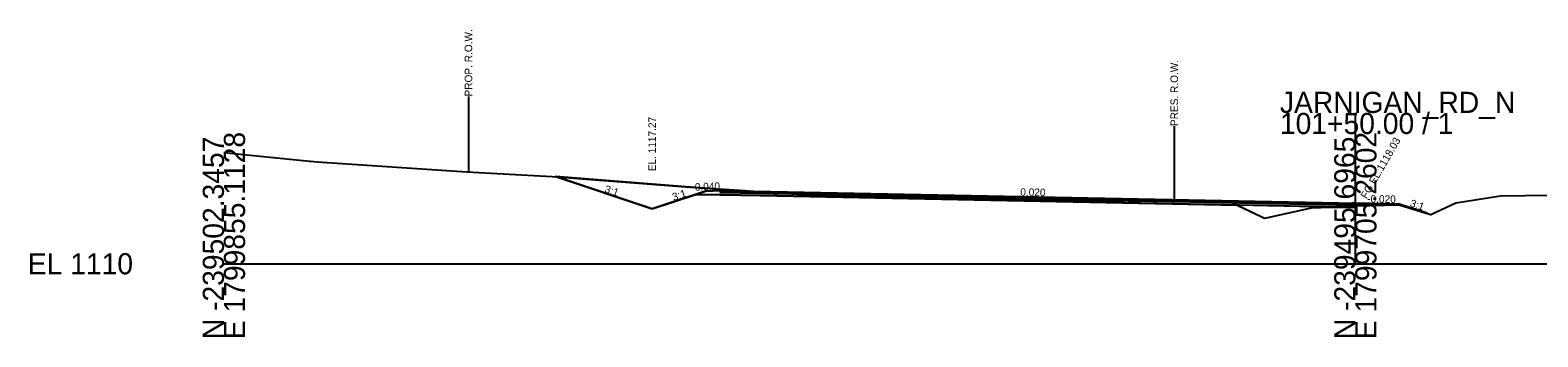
# Model space of a CAD drawing. Extents: x 214513 to 217151, y 214739 to 216780.
# Drawn here: x 216122.7 to 216322.6, y 214738.7 to 214779.3 of the extents above; entities that cross this region are included whole.
import ezdxf

# ---------------------------------------------------------------- set-up
doc = ezdxf.new("R2010")
doc.units = 0
for name, color, linetype in [('CONCEPT - TRANSPORTATION - Roads Text', 7, 'Continuous'), ('DESIGN - CENTERLINE - Proposed', 7, 'Continuous'), ('DESIGN - CENTERLINE - Proposed Text', 7, 'Continuous'), ('DESIGN - DRAINAGE - Special Ditches', 7, 'Continuous'), ('DESIGN - EARTHWORK - Shapes', 7, 'Continuous'), ('DESIGN - ROW - Right-of-Way Linework', 7, 'Continuous'), ('DESIGN - TRANSPORTATION - Text', 7, 'Continuous'), ('DESIGN - TYPICAL - Slope Tie Text', 7, 'Continuous'), ('Section', 7, 'Continuous'), ('SURVEY - DTM GRAPHICS - Triangles', 7, 'Continuous'), ('SURVEY - PROPERTY - ROW Lines', 7, 'Continuous'), ('XSCell', 7, 'Continuous')]:
    doc.layers.add(name, color=color, linetype=linetype)

msp = doc.modelspace()

# ---------------------------------------------------------------- linework, layer by layer
at = {"layer": 'DESIGN - DRAINAGE - Special Ditches'}
for points in [[(216205.13, 214755.64), (216192.3, 214759.92)], [(216212.21, 214758), (216205.13, 214755.64)], [(216214.21, 214758.08), (216214.21, 214757.83), (216219.5, 214757.72), (216298.36, 214756.14), (216298.36, 214755.81), (216219.5, 214757.39), (216214.21, 214757.5), (216210.91, 214757.56), (216212.21, 214758), (216214.21, 214758.08)], [(216214.21, 214758.08), (216298.36, 214756.39), (216298.36, 214756.29), (216298.36, 214756.29), (216214.21, 214757.98), (216214.21, 214757.98), (216214.21, 214757.98), (216214.21, 214758.08), (216214.21, 214758.08)], [(216214.21, 214757.98), (216298.36, 214756.29), (216298.36, 214756.14), (216298.36, 214756.14), (216214.21, 214757.83), (216214.21, 214757.83), (216214.21, 214757.83), (216214.21, 214757.98), (216214.21, 214757.98)], [(216304.16, 214756.28), (216298.36, 214756.39), (216298.36, 214756.29), (216298.36, 214756.29), (216304.16, 214756.18), (216304.16, 214756.18), (216304.16, 214756.18), (216304.16, 214756.28), (216304.16, 214756.28)], [(216304.16, 214756.28), (216307.86, 214755.05)]]:
    msp.add_lwpolyline(points, dxfattribs=at)
at = {"layer": 'DESIGN - EARTHWORK - Shapes'}
for p, q in [((216192.3, 214759.92), (216205.13, 214755.64)), ((216212.21, 214758), (216210.91, 214757.56)), ((216212.21, 214758), (216214.21, 214758.08)), ((216214.21, 214758.08), (216212.21, 214758)), ((216214.21, 214758.08), (216217.4, 214758.01)), ((216214.21, 214757.98), (216214.21, 214758.08)), ((216214.21, 214758.08), (216214.21, 214757.98)), ((216217.4, 214758.01), (216214.21, 214758.08)), ((216219.71, 214757.87), (216214.21, 214757.98)), ((216214.21, 214757.98), (216214.21, 214757.83)), ((216214.21, 214757.98), (216219.71, 214757.87)), ((216214.21, 214757.83), (216219.5, 214757.72)), ((216219.71, 214757.87), (216217.4, 214758.01)), ((216219.5, 214757.72), (216223.18, 214757.65)), ((216223.18, 214757.65), (216219.71, 214757.87)), ((216282, 214756.47), (216276.27, 214756.59)), ((216282.72, 214756.13), (216282, 214756.47)), ((216298.36, 214756.29), (216298.36, 214756.14)), ((216307.86, 214755.05), (216304.16, 214756.28)), ((216295.06, 214755.88), (216282.72, 214756.13)), ((216295.06, 214755.88), (216298.36, 214755.81)), ((216298.36, 214756.14), (216298.36, 214756.05)), ((216298.36, 214755.81), (216298.36, 214756.05))]:
    msp.add_line(p, q, dxfattribs=at)
for points in [[(216217.4, 214758.01), (216215.28, 214758.15), (216209.6, 214758.56), (216192.3, 214759.92)], [(216205.13, 214755.64), (216210.91, 214757.56), (216212.21, 214758)], [(216210.91, 214757.56), (216214.21, 214757.5), (216219.5, 214757.39), (216282.72, 214756.13)], [(216223.18, 214757.65), (216219.5, 214757.72), (216214.21, 214757.83), (216214.21, 214757.98)], [(216276.27, 214756.59), (216268.96, 214756.69), (216268.19, 214756.69), (216246.25, 214757.01), (216226.4, 214757.44), (216223.18, 214757.65)], [(216304.16, 214756.28), (216304.16, 214756.18), (216298.36, 214756.29)], [(216282.72, 214756.13), (216285.94, 214754.6), (216286.3, 214754.42), (216286.75, 214754.51), (216292.55, 214755.76), (216295.06, 214755.88)], [(216298.36, 214756.05), (216297.16, 214755.99), (216295.06, 214755.88)], [(216298.36, 214756.05), (216298.62, 214756.06), (216300.29, 214756.09), (216304.16, 214756.17), (216307.86, 214755.05)]]:
    msp.add_lwpolyline(points, dxfattribs=at)
at = {"layer": 'DESIGN - ROW - Right-of-Way Linework'}
msp.add_lwpolyline([(216180.78, 214770.54), (216180.78, 214760.54)], dxfattribs=at)
at = {"layer": 'SURVEY - DTM GRAPHICS - Triangles'}
msp.add_lwpolyline([(216148.36, 214763.12), (216159.3, 214762.01), (216159.65, 214761.98), (216159.86, 214761.96), (216160.73, 214761.89), (216180.58, 214760.55), (216185.36, 214760.27), (216191.89, 214759.95), (216209.6, 214758.56), (216215.28, 214758.15), (216226.4, 214757.44), (216246.25, 214757.01), (216268.19, 214756.69), (216268.96, 214756.69), (216281.93, 214756.5), (216285.94, 214754.6), (216286.3, 214754.42), (216286.75, 214754.51), (216292.55, 214755.76), (216297.16, 214755.99), (216298.62, 214756.06), (216300.29, 214756.09), (216304.16, 214756.17), (216308.3, 214754.91), (216308.34, 214754.9), (216308.37, 214754.91), (216311.69, 214756.43), (216314.49, 214756.89), (216317.59, 214757.36), (216324.13, 214757.46)], dxfattribs=at)
at = {"layer": 'SURVEY - PROPERTY - ROW Lines'}
msp.add_lwpolyline([(216274.35, 214766.62), (216274.35, 214756.62)], dxfattribs=at)
at = {"layer": 'XSCell'}
for p, q in [((216298.36, 214748.36), (216298.36, 214768.36)), ((216148.36, 214748.36), (216298.36, 214748.36)), ((216298.36, 214748.36), (216448.36, 214748.36))]:
    msp.add_line(p, q, dxfattribs=at)

# ---------------------------------------------------------------- texts
at = {"layer": 'CONCEPT - TRANSPORTATION - Roads Text'}
for s, rotation, p in [('-0.040', 2.2906, (216210.36, 214758.02)), ('0.020', 358.8542, (216253.93, 214757.38)), ('-0.020', 358.8542, (216299.92, 214756.49))]:
    msp.add_text(s, height=1, rotation=rotation, dxfattribs=at).set_placement(p)
at = {"layer": 'DESIGN - CENTERLINE - Proposed'}
msp.add_text('EL. 1117.27', height=1, rotation=90, dxfattribs=at).set_placement((216205.63, 214760.63))
at = {"layer": 'DESIGN - CENTERLINE - Proposed Text'}
msp.add_text('FG EL.1118.03', height=1, rotation=60, dxfattribs=at).set_placement((216299.86, 214756.89))
at = {"layer": 'DESIGN - TRANSPORTATION - Text'}
for s, p in [('PROP. R.O.W.', (216181.28, 214770.54)), ('PRES. R.O.W.', (216274.85, 214766.62))]:
    msp.add_text(s, height=1, rotation=90, dxfattribs=at).set_placement(p)
at = {"layer": 'DESIGN - TYPICAL - Slope Tie Text'}
for rotation, p in [(341.5651, (216198.75, 214757.87)), (18.4349, (216207.99, 214756.7)), (341.5652, (216305.53, 214755.98))]:
    msp.add_text('3:1', height=1, rotation=rotation, dxfattribs=at).set_placement(p)
at = {"layer": 'Section'}
msp.add_text('-', height=0.0001, dxfattribs=at).set_placement((216148.36, 214748.36))
at = {"layer": 'XSCell'}
for s, p in [('JARNIGAN_RD_N', (216288.36, 214768.36)), ('101+50.00 / 1', (216288.36, 214765.56)), ('EL 1110', (216122.36, 214746.96))]:
    msp.add_text(s, height=2.8, dxfattribs=at).set_placement(p)
for s, p in [('N -239502.3457', (216148.36, 214738.36)), ('E 1799855.1128', (216151.16, 214738.36)), ('N -239495.6965', (216298.36, 214738.36)), ('E 1799705.2602', (216301.16, 214738.36))]:
    msp.add_text(s, height=2.8, rotation=90, dxfattribs=at).set_placement(p)

doc.saveas('drawing.dxf')
